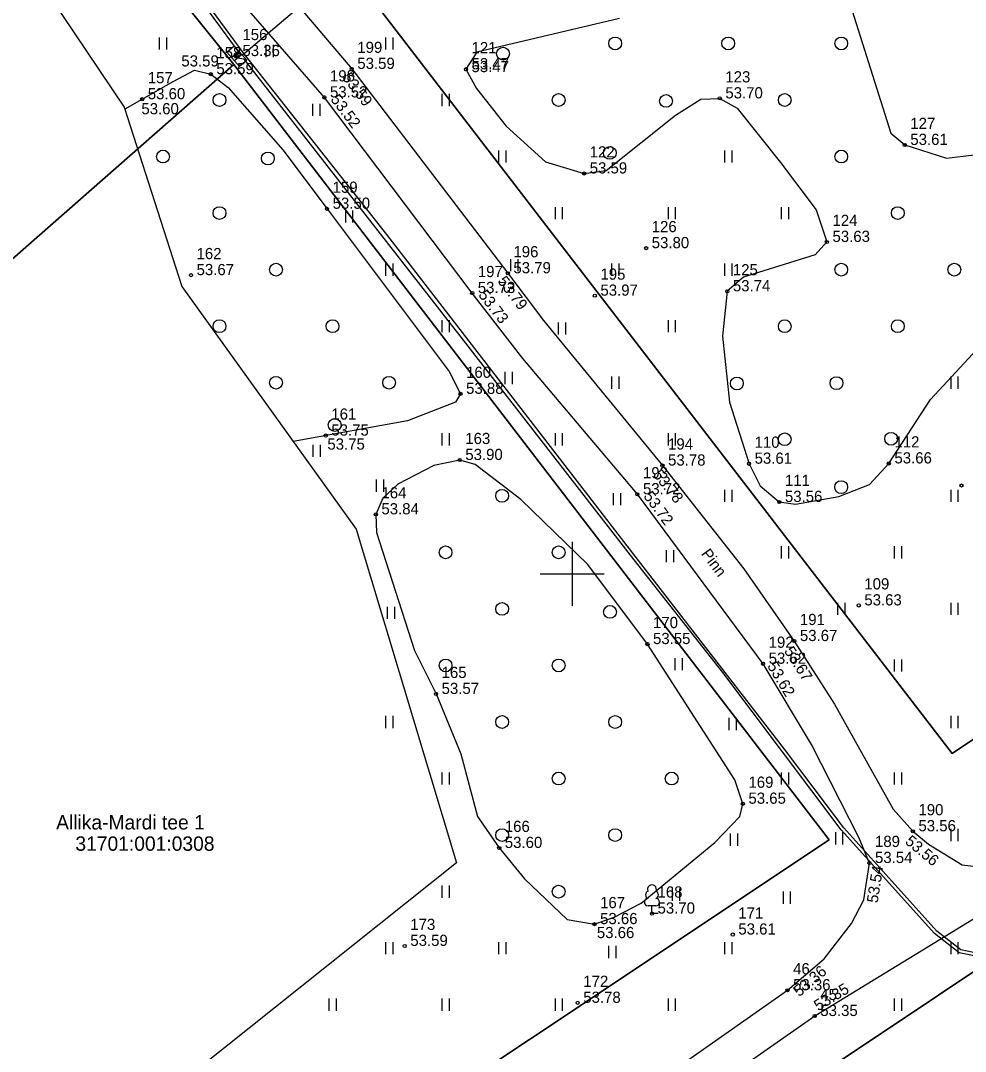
# Model space of a CAD drawing. Extents: x 538599 to 541973, y 6559689 to 6564516.
# Drawn here: x 540515.5 to 540574.6, y 6561220.1 to 6561284.6 of the extents above; entities that cross this region are included whole.
import ezdxf

# ---------------------------------------------------------------- set-up
doc = ezdxf.new("R2010")
doc.units = 0
for name, color, linetype in [('ELRAJATISMP', 7, 'Continuous'), ('HALJASTUS', 7, 'Continuous'), ('KORGUS-EH2000', 7, 'Continuous'), ('KPKAABEL', 7, 'Continuous'), ('MOOTKORG-EH2000', 7, 'Continuous'), ('MOOTMPUNKT', 7, 'Continuous'), ('MOOTNR', 7, 'Continuous'), ('MOOTPIIR', 7, 'Continuous'), ('MPKAABEL', 7, 'Continuous'), ('PIIR', 7, 'Continuous'), ('PUU', 7, 'Continuous'), ('TEE', 7, 'Continuous'), ('VORK', 7, 'Continuous')]:
    doc.layers.add(name, color=color, linetype=linetype)

msp = doc.modelspace()

# ---------------------------------------------------------------- linework, layer by layer
at = {"layer": 'ELRAJATISMP'}
for p, q in [((540529.164, 6561282.662), (540528.713, 6561282.271)), ((540529.341, 6561282.457), (540528.89, 6561282.066))]:
    msp.add_line(p, q, dxfattribs=at)
msp.add_lwpolyline([(540528.862, 6561283.011), (540529.644, 6561282.108), (540529.192, 6561281.717), (540528.41, 6561282.62)], close=True, dxfattribs=at)
at = {"layer": 'HALJASTUS'}
for p, q in [((540524.179, 6561283.536), (540524.179, 6561282.775)), ((540524.634, 6561283.536), (540524.634, 6561282.775)), ((540538.321, 6561283.536), (540538.321, 6561282.775)), ((540538.776, 6561283.536), (540538.776, 6561282.775)), ((540530.834, 6561283.07), (540530.834, 6561282.308)), ((540531.29, 6561283.07), (540531.29, 6561282.308)), ((540541.857, 6561280), (540541.857, 6561279.239)), ((540542.312, 6561280), (540542.312, 6561279.239)), ((540533.769, 6561279.389), (540533.769, 6561278.628)), ((540534.224, 6561279.389), (540534.224, 6561278.628)), ((540545.392, 6561276.465), (540545.392, 6561275.704)), ((540545.847, 6561276.465), (540545.847, 6561275.704)), ((540559.534, 6561276.465), (540559.534, 6561275.704)), ((540559.989, 6561276.465), (540559.989, 6561275.704)), ((540535.815, 6561272.714), (540535.815, 6561271.953)), ((540536.27, 6561272.714), (540536.27, 6561271.953)), ((540548.928, 6561272.929), (540548.928, 6561272.168)), ((540549.383, 6561272.929), (540549.383, 6561272.168)), ((540555.999, 6561272.929), (540555.999, 6561272.168)), ((540556.454, 6561272.929), (540556.454, 6561272.168)), ((540563.07, 6561272.929), (540563.07, 6561272.168)), ((540563.525, 6561272.929), (540563.525, 6561272.168)), ((540538.321, 6561269.394), (540538.321, 6561268.633)), ((540538.776, 6561269.394), (540538.776, 6561268.633)), ((540546.154, 6561269.669), (540546.154, 6561268.908)), ((540546.609, 6561269.669), (540546.609, 6561268.908)), ((540552.463, 6561269.394), (540552.463, 6561268.633)), ((540552.918, 6561269.394), (540552.918, 6561268.633)), ((540559.534, 6561269.394), (540559.534, 6561268.633)), ((540559.989, 6561269.394), (540559.989, 6561268.633)), ((540541.857, 6561265.858), (540541.857, 6561265.097)), ((540542.312, 6561265.858), (540542.312, 6561265.097)), ((540549.135, 6561265.713), (540549.135, 6561264.952)), ((540549.59, 6561265.713), (540549.59, 6561264.952)), ((540555.999, 6561265.858), (540555.999, 6561265.097)), ((540556.454, 6561265.858), (540556.454, 6561265.097)), ((540545.799, 6561262.623), (540545.799, 6561261.862)), ((540546.254, 6561262.623), (540546.254, 6561261.862)), ((540552.463, 6561262.323), (540552.463, 6561261.562)), ((540552.918, 6561262.323), (540552.918, 6561261.562)), ((540573.676, 6561262.323), (540573.676, 6561261.562)), ((540574.131, 6561262.323), (540574.131, 6561261.562)), ((540541.857, 6561258.787), (540541.857, 6561258.026)), ((540542.312, 6561258.787), (540542.312, 6561258.026)), ((540548.928, 6561258.787), (540548.928, 6561258.026)), ((540549.383, 6561258.787), (540549.383, 6561258.026)), ((540555.999, 6561258.787), (540555.999, 6561258.026)), ((540556.454, 6561258.787), (540556.454, 6561258.026)), ((540533.79, 6561258.066), (540533.79, 6561257.305)), ((540534.245, 6561258.066), (540534.245, 6561257.305)), ((540537.745, 6561255.891), (540537.745, 6561255.13)), ((540538.2, 6561255.891), (540538.2, 6561255.13)), ((540559.534, 6561255.252), (540559.534, 6561254.491)), ((540559.989, 6561255.252), (540559.989, 6561254.491)), ((540573.676, 6561255.252), (540573.676, 6561254.491)), ((540574.131, 6561255.252), (540574.131, 6561254.491)), ((540552.569, 6561255.042), (540552.569, 6561254.281)), ((540553.024, 6561255.042), (540553.024, 6561254.281)), ((540555.882, 6561251.48), (540555.882, 6561250.719)), ((540556.337, 6561251.48), (540556.337, 6561250.719)), ((540563.07, 6561251.716), (540563.07, 6561250.955)), ((540563.525, 6561251.716), (540563.525, 6561250.955)), ((540570.141, 6561251.716), (540570.141, 6561250.955)), ((540570.596, 6561251.716), (540570.596, 6561250.955)), ((540566.605, 6561248.181), (540566.605, 6561247.42)), ((540567.06, 6561248.181), (540567.06, 6561247.42)), ((540573.676, 6561248.181), (540573.676, 6561247.42)), ((540574.131, 6561248.181), (540574.131, 6561247.42)), ((540538.428, 6561247.938), (540538.428, 6561247.177)), ((540538.883, 6561247.938), (540538.883, 6561247.177)), ((540556.42, 6561244.728), (540556.42, 6561243.967)), ((540556.875, 6561244.728), (540556.875, 6561243.967)), ((540570.141, 6561244.645), (540570.141, 6561243.884)), ((540570.596, 6561244.645), (540570.596, 6561243.884)), ((540538.321, 6561241.11), (540538.321, 6561240.348)), ((540538.776, 6561241.11), (540538.776, 6561240.348)), ((540573.676, 6561241.11), (540573.676, 6561240.348)), ((540574.131, 6561241.11), (540574.131, 6561240.348)), ((540559.795, 6561240.979), (540559.795, 6561240.218)), ((540560.25, 6561240.979), (540560.25, 6561240.218)), ((540541.857, 6561237.574), (540541.857, 6561236.813)), ((540542.312, 6561237.574), (540542.312, 6561236.813)), ((540563.07, 6561237.574), (540563.07, 6561236.813)), ((540563.525, 6561237.574), (540563.525, 6561236.813)), ((540570.141, 6561237.574), (540570.141, 6561236.813)), ((540570.596, 6561237.574), (540570.596, 6561236.813)), ((540573.676, 6561234.039), (540573.676, 6561233.277)), ((540574.131, 6561234.039), (540574.131, 6561233.277)), ((540559.878, 6561233.751), (540559.878, 6561232.99)), ((540560.333, 6561233.751), (540560.333, 6561232.99)), ((540566.462, 6561233.833), (540566.462, 6561233.072)), ((540566.917, 6561233.833), (540566.917, 6561233.072)), ((540541.857, 6561230.503), (540541.857, 6561229.742)), ((540542.312, 6561230.503), (540542.312, 6561229.742)), ((540556.255, 6561230.312), (540556.255, 6561229.551)), ((540556.71, 6561230.312), (540556.71, 6561229.551)), ((540563.191, 6561230.126), (540563.191, 6561229.365)), ((540563.646, 6561230.126), (540563.646, 6561229.365)), ((540538.321, 6561226.967), (540538.321, 6561226.206)), ((540538.776, 6561226.967), (540538.776, 6561226.206)), ((540545.392, 6561226.967), (540545.392, 6561226.206)), ((540545.847, 6561226.967), (540545.847, 6561226.206)), ((540559.534, 6561226.967), (540559.534, 6561226.206)), ((540559.989, 6561226.967), (540559.989, 6561226.206)), ((540573.676, 6561226.967), (540573.676, 6561226.206)), ((540574.131, 6561226.967), (540574.131, 6561226.206)), ((540552.279, 6561226.729), (540552.279, 6561225.968)), ((540552.734, 6561226.729), (540552.734, 6561225.968)), ((540534.785, 6561223.432), (540534.785, 6561222.671)), ((540535.241, 6561223.432), (540535.241, 6561222.671)), ((540541.857, 6561223.432), (540541.857, 6561222.671)), ((540542.312, 6561223.432), (540542.312, 6561222.671)), ((540548.928, 6561223.432), (540548.928, 6561222.671)), ((540549.383, 6561223.432), (540549.383, 6561222.671)), ((540555.999, 6561223.432), (540555.999, 6561222.671)), ((540556.454, 6561223.432), (540556.454, 6561222.671)), ((540570.141, 6561223.432), (540570.141, 6561222.671)), ((540570.596, 6561223.432), (540570.596, 6561222.671))]:
    msp.add_line(p, q, dxfattribs=at)
for points in [[(540570.802, 6561276.809), (540573.412, 6561275.976), (540576.87, 6561276.39), (540577.836, 6561277.043), (540578.505, 6561278.71), (540578.609, 6561282.748), (540578.298, 6561287.056), (540577.866, 6561289.9), (540576.248, 6561292.214), (540572.273, 6561295.155), (540567.268, 6561297.994), (540566.387, 6561298.177), (540565.922, 6561297.598), (540564.985, 6561294.225), (540565.068, 6561290.756), (540565.634, 6561288.817), (540567.508, 6561285.194), (540569.933, 6561277.546), (540570.802, 6561276.809)], [(540552.955, 6561284.718), (540544.046, 6561282.606), (540543.357, 6561281.544), (540544.025, 6561280.348), (540545.868, 6561277.987), (540548.342, 6561275.75), (540550.75, 6561275.026), (540552.121, 6561275.211), (540556.469, 6561278.662), (540558.048, 6561279.664), (540559.234, 6561279.721), (540560.32, 6561279.105), (540563.041, 6561275.707), (540565.265, 6561272.745), (540565.935, 6561270.745), (540565.192, 6561269.942), (540560.719, 6561268.546), (540559.704, 6561267.658), (540559.403, 6561264.857), (540559.838, 6561260.727), (540561.062, 6561256.876)], [(540561.062, 6561256.876), (540561.766, 6561255.487), (540562.959, 6561254.486), (540563.979, 6561254.35), (540566.676, 6561254.836), (540568.605, 6561255.581), (540569.809, 6561256.895), (540572.418, 6561260.901), (540575.042, 6561263.719), (540586.108, 6561271.474), (540587.537, 6561273.178), (540588.329, 6561274.808), (540590.147, 6561281.335), (540590.644, 6561284.753)], [(540522.05, 6561279.069), (540525.053, 6561280.771), (540526.389, 6561281.484), (540527.397, 6561281.234), (540528.49, 6561280.396), (540531.91, 6561276.506), (540534.669, 6561272.817), (540542.306, 6561262.654), (540543.016, 6561261.247), (540542.704, 6561260.736), (540539.698, 6561259.553), (540532.554, 6561258.272)], [(540554.708, 6561245.6), (540550.98, 6561250.571), (540546.798, 6561254.651), (540543.941, 6561256.826), (540542.967, 6561257.109), (540541.346, 6561256.764), (540539.096, 6561255.604), (540538.164, 6561254.719), (540537.721, 6561253.712), (540537.771, 6561252.58), (540540.15, 6561245.209), (540541.485, 6561242.481), (540543.037, 6561238.741), (540544.084, 6561234.814), (540545.439, 6561232.853), (540547.024, 6561230.912), (540549.683, 6561228.385), (540551.398, 6561228.088), (540552.635, 6561228.53), (540554.312, 6561229.4), (540558.929, 6561233.19), (540560.482, 6561234.829), (540560.677, 6561235.616), (540560.172, 6561237.105), (540554.708, 6561245.6)]]:
    msp.add_lwpolyline(points, dxfattribs=at)
for centre in [(540552.691, 6561283.155), (540559.762, 6561283.155), (540566.833, 6561283.155), (540545.679, 6561282.515), (540527.942, 6561279.62), (540549.155, 6561279.62), (540555.873, 6561279.563), (540563.297, 6561279.62), (540524.406, 6561276.084), (540552.354, 6561276.311), (540566.833, 6561276.084), (540530.969, 6561275.964), (540527.942, 6561272.549), (540570.368, 6561272.549), (540531.477, 6561269.013), (540566.833, 6561269.013), (540573.904, 6561269.013), (540527.942, 6561265.478), (540535.013, 6561265.478), (540563.297, 6561265.478), (540570.368, 6561265.478), (540531.477, 6561261.942), (540538.549, 6561261.942), (540560.304, 6561261.895), (540566.536, 6561261.916), (540535.147, 6561259.301), (540563.297, 6561258.407), (540569.952, 6561258.437), (540566.826, 6561255.413), (540545.62, 6561254.871), (540542.084, 6561251.336), (540549.155, 6561251.336), (540545.62, 6561247.8), (540552.366, 6561247.615), (540542.084, 6561244.264), (540549.155, 6561244.264), (540545.62, 6561240.729), (540552.691, 6561240.729), (540549.155, 6561237.193), (540556.226, 6561237.193), (540545.62, 6561233.658), (540552.691, 6561233.658), (540549.155, 6561230.122)]:
    msp.add_circle(centre, 0.4, dxfattribs=at)
at = {"layer": 'KORGUS-EH2000'}
for centre in [(540536.213, 6561281.563), (540543.357, 6561281.544), (540527.397, 6561281.234), (540523.107, 6561279.668), (540534.504, 6561279.782), (540559.234, 6561279.721), (540570.802, 6561276.809), (540534.669, 6561272.817), (540565.935, 6561270.745), (540554.628, 6561270.355), (540526.159, 6561268.668), (540545.977, 6561268.786), (540543.75, 6561267.549), (540551.42, 6561267.384), (540543.016, 6561261.247), (540534.589, 6561258.637), (540542.967, 6561257.109), (540555.649, 6561256.763), (540561.062, 6561256.876), (540574.353, 6561255.517), (540554.081, 6561254.966), (540537.721, 6561253.712), (540567.926, 6561248.018), (540554.708, 6561245.6), (540563.896, 6561245.79), (540561.94, 6561244.368), (540541.485, 6561242.481), (540560.677, 6561235.616), (540571.311, 6561233.896), (540545.439, 6561232.853), (540568.593, 6561231.912), (540551.398, 6561228.088), (540560.046, 6561227.438), (540539.528, 6561226.726), (540563.47, 6561223.953), (540550.347, 6561223.168), (540565.171, 6561222.344)]:
    msp.add_circle(centre, 0.1, dxfattribs=at)
at = {"layer": 'KPKAABEL'}
msp.add_lwpolyline([(540612.707, 6561251.641), (540589.754, 6561235.922), (540575.113, 6561226.32), (540574.309, 6561226.488), (540572.813, 6561227.652), (540566.988, 6561234.121), (540563.285, 6561239.03), (540553.802, 6561251.292), (540538.41, 6561271.219), (540529.488, 6561282.512), (540526.272, 6561286.879), (540510.559, 6561306.203), (540484.617, 6561338.574), (540463.547, 6561364.405), (540438.892, 6561393.697), (540425.441, 6561409.211), (540424.922, 6561409.461), (540423.725, 6561408.808), (540421.719, 6561406.34), (540419.82, 6561404.72)], dxfattribs=at)
at = {"layer": 'MOOTMPUNKT'}
for centre in [(540529.027, 6561282.364), (540536.213, 6561281.563), (540543.357, 6561281.544), (540527.397, 6561281.234), (540523.107, 6561279.668), (540534.504, 6561279.782), (540559.234, 6561279.721), (540570.802, 6561276.809), (540550.75, 6561275.026), (540534.669, 6561272.817), (540565.935, 6561270.745), (540554.628, 6561270.355), (540526.159, 6561268.668), (540545.977, 6561268.786), (540543.75, 6561267.549), (540551.42, 6561267.384), (540559.704, 6561267.658), (540543.016, 6561261.247), (540534.589, 6561258.637), (540542.967, 6561257.109), (540555.649, 6561256.763), (540561.062, 6561256.876), (540569.809, 6561256.895), (540574.353, 6561255.517), (540554.081, 6561254.966), (540562.959, 6561254.486), (540537.721, 6561253.712), (540567.926, 6561248.018), (540554.708, 6561245.6), (540563.896, 6561245.79), (540561.94, 6561244.368), (540541.485, 6561242.481), (540560.677, 6561235.616), (540571.311, 6561233.896), (540545.439, 6561232.853), (540568.593, 6561231.912), (540554.992, 6561228.751), (540551.398, 6561228.088), (540560.046, 6561227.438), (540539.528, 6561226.726), (540563.47, 6561223.953), (540550.347, 6561223.168), (540565.171, 6561222.344)]:
    msp.add_circle(centre, 0.1, dxfattribs=at)
at = {"layer": 'MOOTPIIR'}
msp.add_lwpolyline([(540384.887, 6561443.845), (540403.973, 6561422.469), (540424.304, 6561399.698), (540444.636, 6561376.927), (540453.177, 6561363.987), (540470.995, 6561343.689), (540492.689, 6561318.976), (540511.766, 6561294.341), (540521.974, 6561279.181), (540525.589, 6561267.954), (540536.495, 6561252.794), (540542.772, 6561231.926), (540526.603, 6561219.05), (540510.624, 6561213.468), (540498.26, 6561199.196), (540484.564, 6561192.98), (540479.618, 6561185.622), (540478.413, 6561178.328), (540490.461, 6561165.832), (540493.58, 6561162.597), (540531.105, 6561187.906), (540582.869, 6561222.817), (540621.742, 6561247.747)], dxfattribs=at)
at = {"layer": 'MPKAABEL'}
for points in [[(540624.746, 6561259.652), (540607.46, 6561247.735), (540595.988, 6561239.875), (540585.355, 6561232.862), (540575.156, 6561226.105), (540574.211, 6561226.297), (540572.668, 6561227.5), (540566.836, 6561233.992), (540559.418, 6561243.82), (540553.652, 6561251.158), (540543.068, 6561264.797), (540529.488, 6561282.18), (540528.898, 6561282.254), (540529.176, 6561282.594), (540526.037, 6561286.855), (540522.472, 6561291.297), (540514.38, 6561301.154), (540496.217, 6561323.662), (540475.169, 6561349.87)], [(540535.521, 6561287.638), (540529.488, 6561282.512), (540528.898, 6561282.254)]]:
    msp.add_lwpolyline(points, dxfattribs=at)
at = {"layer": 'PIIR'}
for points in [[(540491.21, 6561183.5), (540566.07, 6561233.36), (540528.84, 6561281.85), (540494.34, 6561324.62), (540458.27, 6561368.69), (540424.68, 6561408.57), (540384.55, 6561455.73), (540346.17, 6561499.11), (540330.12, 6561517.14), (540337.36, 6561523.32), (540348.28, 6561532.96), (540364.11, 6561514.94), (540353.14, 6561505.27), (540391.51, 6561461.86), (540431.74, 6561414.74), (540465.17, 6561374.89), (540501.31, 6561330.86), (540535.92, 6561287.97), (540573.77, 6561238.75), (540640.63, 6561283.66), (540646.74, 6561272.89), (540499, 6561174.36)], [(540535.92, 6561287.97), (540606.26, 6561333.96), (540640.63, 6561283.66), (540573.77, 6561238.75)], [(540422.29, 6561261.69), (540494.34, 6561324.62), (540528.84, 6561281.85), (540458.8, 6561220.37)], [(540458.8, 6561220.37), (540528.84, 6561281.85), (540566.07, 6561233.36), (540491.21, 6561183.5)], [(540490.55, 6561169.03), (540499, 6561174.36), (540646.74, 6561272.89), (540687.02, 6561204.55), (540544.29, 6561102.63)]]:
    msp.add_lwpolyline(points, close=True, dxfattribs=at)
at = {"layer": 'PUU'}
for p, q in [((540555.232, 6561229.226), (540554.752, 6561229.226)), ((540554.992, 6561228.751), (540554.992, 6561229.226)), ((540555.372, 6561228.751), (540554.992, 6561228.751))]:
    msp.add_line(p, q, dxfattribs=at)
for centre, radius, start, end in [((540554.822, 6561229.924), 0.233, 109.02174, 253.14154), ((540554.992, 6561230.271), 0.277, 332.5799, 207.4201), ((540555.162, 6561229.924), 0.233, 286.85082, 70.98591), ((540554.755, 6561229.463), 0.238, 90.0016, 269.3953), ((540555.229, 6561229.463), 0.238, 270.6047, 89.9984)]:
    msp.add_arc(centre, radius, start, end, dxfattribs=at)
at = {"layer": 'TEE'}
for points in [[(540480.237, 6561350.173), (540490.343, 6561338.333), (540499.283, 6561327.538), (540509.455, 6561315.157), (540515.302, 6561308.183), (540518.538, 6561303.936), (540527.782, 6561291.781), (540530.574, 6561288.237), (540536.213, 6561281.563), (540545.977, 6561268.786), (540548.214, 6561265.824), (540555.649, 6561256.763), (540560.731, 6561250.307), (540563.896, 6561245.79), (540566.417, 6561241.84), (540570.085, 6561235.281), (540571.311, 6561233.896), (540572.286, 6561233.082), (540574.391, 6561231.792), (540575.618, 6561231.655), (540576.368, 6561231.987), (540586.536, 6561238.83), (540599.72, 6561247.482), (540611.437, 6561255.604)], [(540551.357, 6561215.457), (540563.47, 6561223.953), (540565.768, 6561225.916), (540567.471, 6561228.123), (540568.24, 6561229.603), (540568.593, 6561231.912), (540567.955, 6561233.461), (540564.971, 6561239.313), (540561.94, 6561244.368), (540554.081, 6561254.966), (540546.908, 6561263.448), (540543.75, 6561267.549), (540534.504, 6561279.782), (540528.673, 6561286.519), (540525.77, 6561290.154), (540516.79, 6561301.878), (540507.075, 6561313.531), (540497.508, 6561325.645), (540488.154, 6561336.579), (540478.587, 6561348.431)], [(540651.018, 6561277.76), (540649.299, 6561277.32), (540647.947, 6561276.705), (540637.204, 6561268.881), (540625.631, 6561261.527), (540617.283, 6561256.229), (540613.091, 6561253.422), (540601.001, 6561245.406), (540588.333, 6561236.983), (540576.973, 6561229.557), (540565.171, 6561222.344), (540552.563, 6561213.52), (540540.165, 6561205.325), (540527.674, 6561197.002), (540515.613, 6561188.752), (540503.253, 6561180.454), (540486.571, 6561169.867)]]:
    msp.add_lwpolyline(points, dxfattribs=at)
at = {"layer": 'VORK'}
for p, q in [((540550, 6561252), (540550, 6561248)), ((540548, 6561250), (540552, 6561250))]:
    msp.add_line(p, q, dxfattribs=at)

# ---------------------------------------------------------------- texts
at = {"layer": 'KORGUS-EH2000'}
for s, p in [('53.59', (540525.557, 6561281.714)), ('53.47', (540543.707, 6561281.361)), ('53.70', (540559.584, 6561279.721)), ('53.60', (540523.058, 6561278.728)), ('53.61', (540571.152, 6561276.809)), ('53.50', (540535.019, 6561272.817)), ('53.63', (540566.285, 6561270.745)), ('53.80', (540554.978, 6561270.355)), ('53.67', (540526.509, 6561268.668)), ('53.97', (540551.77, 6561267.384)), ('53.88', (540543.366, 6561261.247)), ('53.75', (540534.691, 6561257.758)), ('53.90', (540543.317, 6561257.109)), ('53.61', (540561.412, 6561256.876)), ('53.84', (540538.071, 6561253.712)), ('53.63', (540568.276, 6561248.018)), ('53.55', (540555.058, 6561245.6)), ('53.57', (540541.835, 6561242.481)), ('53.65', (540561.027, 6561235.616)), ('53.60', (540545.789, 6561232.853)), ('53.61', (540560.396, 6561227.438)), ('53.66', (540551.547, 6561227.215)), ('53.59', (540539.878, 6561226.726)), ('53.78', (540550.697, 6561223.168))]:
    msp.add_text(s, height=0.7, dxfattribs=at).set_placement(p)
for s, rotation, p in [('53.59', 307.38654, (540535.583, 6561281.015)), ('53.52', 307.08288, (540534.854, 6561279.654)), ('53.79', 307.06442, (540545.299, 6561268.286)), ('53.73', 307.59839, (540544.1, 6561267.421)), ('53.78', 308.21095, (540555.019, 6561256.181)), ('53.72', 306.55897, (540554.431, 6561254.838)), ('53.67', 302.54807, (540563.228, 6561245.172)), ('53.62', 300.9453, (540562.178, 6561244.237)), ('53.56', 320.16025, (540570.774, 6561233.174)), ('53.54', 81.30018, (540569.109, 6561229.379)), ('53.36', 40.50347, (540564.199, 6561223.513)), ('53.35', 31.43192, (540565.393, 6561222.628))]:
    msp.add_text(s, height=0.7, rotation=rotation, dxfattribs=at).set_placement(p)
at = {"layer": 'MOOTKORG-EH2000'}
for s, p in [('53.36', (540529.377, 6561282.364)), ('53.59', (540536.563, 6561281.563)), ('53.47', (540543.707, 6561281.544)), ('53.59', (540527.747, 6561281.234)), ('53.60', (540523.457, 6561279.668)), ('53.52', (540534.854, 6561279.782)), ('53.70', (540559.584, 6561279.721)), ('53.61', (540571.152, 6561276.809)), ('53.59', (540551.1, 6561275.026)), ('53.50', (540535.019, 6561272.817)), ('53.63', (540566.285, 6561270.745)), ('53.80', (540554.978, 6561270.355)), ('53.67', (540526.509, 6561268.668)), ('53.79', (540546.327, 6561268.786)), ('53.73', (540544.1, 6561267.549)), ('53.97', (540551.77, 6561267.384)), ('53.74', (540560.054, 6561267.658)), ('53.88', (540543.366, 6561261.247)), ('53.75', (540534.939, 6561258.637)), ('53.90', (540543.317, 6561257.109)), ('53.78', (540555.999, 6561256.763)), ('53.61', (540561.412, 6561256.876)), ('53.66', (540570.159, 6561256.895)), ('53.72', (540554.431, 6561254.966)), ('53.56', (540563.309, 6561254.486)), ('53.84', (540538.071, 6561253.712)), ('53.63', (540568.276, 6561248.018)), ('53.55', (540555.058, 6561245.6)), ('53.67', (540564.246, 6561245.79)), ('53.62', (540562.29, 6561244.368)), ('53.57', (540541.835, 6561242.481)), ('53.65', (540561.027, 6561235.616)), ('53.56', (540571.661, 6561233.896)), ('53.60', (540545.789, 6561232.853)), ('53.54', (540568.943, 6561231.912)), ('53.70', (540555.342, 6561228.751)), ('53.66', (540551.748, 6561228.088)), ('53.61', (540560.396, 6561227.438)), ('53.59', (540539.878, 6561226.726)), ('53.36', (540563.82, 6561223.953)), ('53.78', (540550.697, 6561223.168)), ('53.35', (540565.521, 6561222.344))]:
    msp.add_text(s, height=0.7, dxfattribs=at).set_placement(p)
at = {"layer": 'MOOTNR'}
for s, p in [('156', (540529.377, 6561283.364)), ('158', (540527.747, 6561282.234)), ('199', (540536.563, 6561282.563)), ('121', (540543.707, 6561282.544)), ('157', (540523.457, 6561280.668)), ('198', (540534.854, 6561280.782)), ('123', (540559.584, 6561280.721)), ('127', (540571.152, 6561277.809)), ('122', (540551.1, 6561276.026)), ('159', (540535.019, 6561273.817)), ('126', (540554.978, 6561271.355)), ('124', (540566.285, 6561271.745)), ('162', (540526.509, 6561269.668)), ('196', (540546.327, 6561269.786)), ('125', (540560.054, 6561268.658)), ('197', (540544.1, 6561268.549)), ('195', (540551.77, 6561268.384)), ('160', (540543.366, 6561262.247)), ('161', (540534.939, 6561259.637)), ('163', (540543.317, 6561258.109)), ('194', (540555.999, 6561257.763)), ('110', (540561.412, 6561257.876)), ('112', (540570.159, 6561257.895)), ('193', (540554.431, 6561255.966)), ('111', (540563.309, 6561255.486)), ('164', (540538.071, 6561254.712)), ('109', (540568.276, 6561249.018)), ('191', (540564.246, 6561246.79)), ('170', (540555.058, 6561246.6)), ('192', (540562.29, 6561245.368)), ('165', (540541.835, 6561243.481)), ('169', (540561.027, 6561236.616)), ('190', (540571.661, 6561234.896)), ('166', (540545.789, 6561233.853)), ('189', (540568.943, 6561232.912)), ('168', (540555.342, 6561229.751)), ('167', (540551.748, 6561229.088)), ('171', (540560.396, 6561228.438)), ('173', (540539.878, 6561227.726)), ('46', (540563.82, 6561224.953)), ('172', (540550.697, 6561224.168)), ('45', (540565.521, 6561223.344))]:
    msp.add_text(s, height=0.7, dxfattribs=at).set_placement(p)
at = {"layer": 'PIIR'}
for s, p in [('Allika-Mardi tee 1', (540517.724, 6561234.007)), ('31701:001:0308', (540518.93, 6561232.675))]:
    msp.add_text(s, height=0.9, rotation=360, dxfattribs=at).set_placement(p)
at = {"layer": 'TEE'}
msp.add_text('Pinn', height=0.7, rotation=306.55897, dxfattribs=at).set_placement((540558.036, 6561251.243))

doc.saveas('drawing.dxf')
